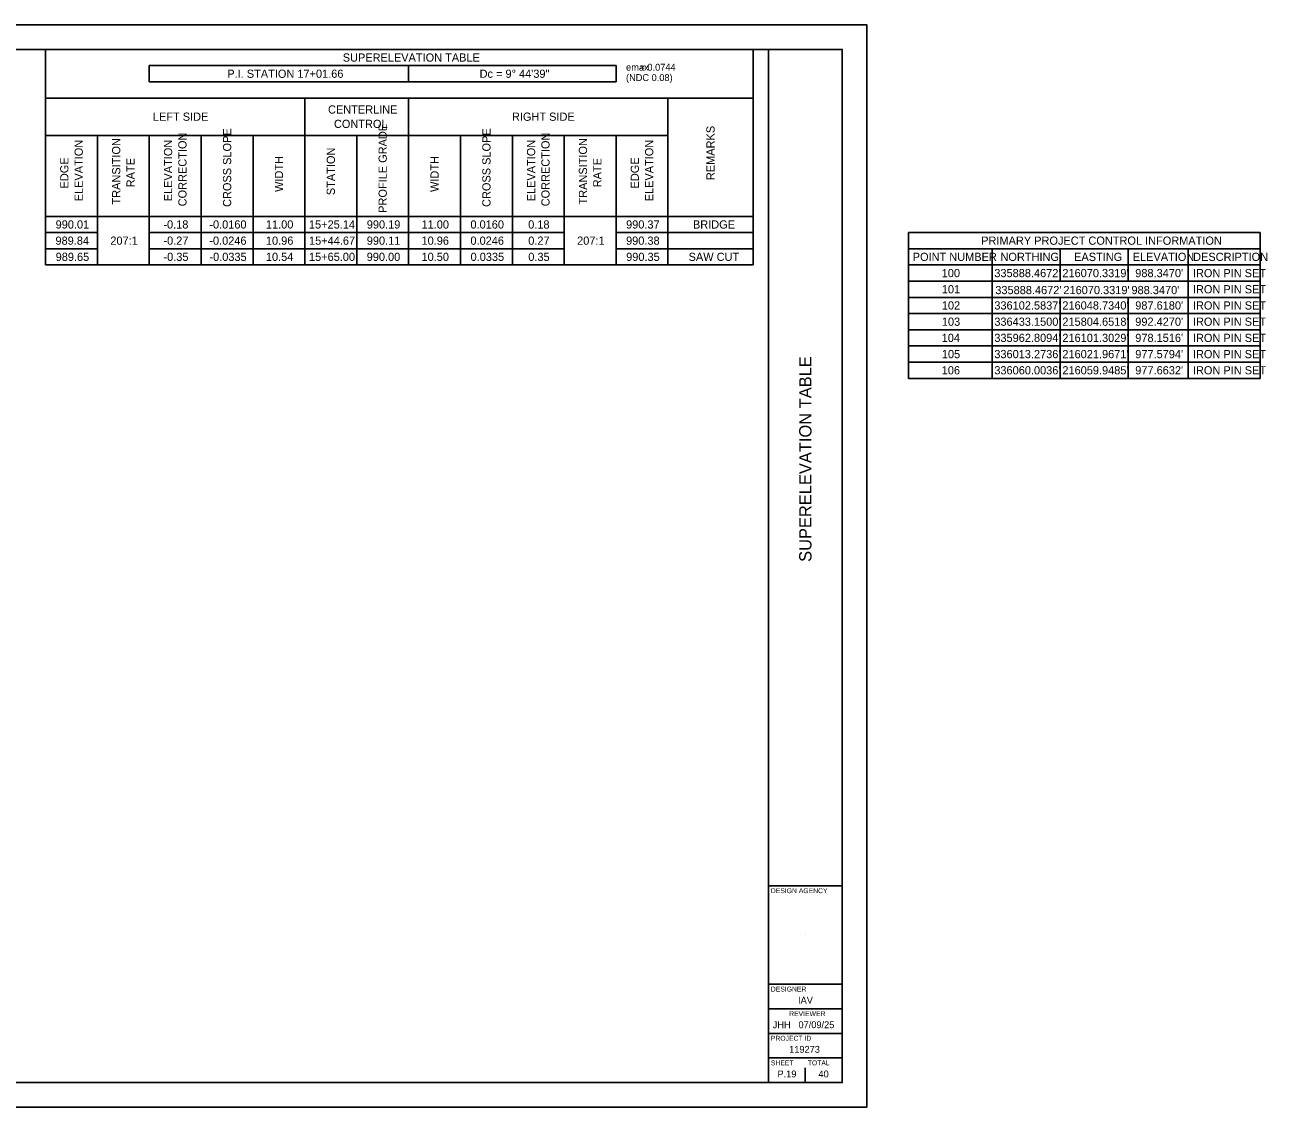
# Model space of a CAD drawing. Extents: x 0 to 42.1, y 0 to 22.
# Drawn here: x 16.89 to 42.14, y 0 to 22 of the extents above; entities that cross this region are included whole.
import ezdxf

# ---------------------------------------------------------------- set-up
doc = ezdxf.new("R2010")
doc.units = 0
for name, color, linetype in [('SH_Border', 7, 'Continuous'), ('SH_Cut_Line', 7, 'Continuous'), ('SH_Data', 7, 'Continuous'), ('SH_Text', 7, 'Continuous')]:
    doc.layers.add(name, color=color, linetype=linetype)

msp = doc.modelspace()

# ---------------------------------------------------------------- linework, layer by layer
at = {"layer": 'SH_Border'}
for p, q in [((32, 0.5), (32, 21.5)), ((32, 4.5), (33.5, 4.5)), ((32, 2.5), (33.5, 2.5)), ((32, 2), (33.5, 2)), ((32, 1.5), (33.5, 1.5)), ((32, 1), (33.5, 1))]:
    msp.add_line(p, q, dxfattribs=at)
msp.add_lwpolyline([(1.5, 21.5), (33.5, 21.5), (33.5, 0.5), (1.5, 0.5)], close=True, dxfattribs=at)
at = {"layer": 'SH_Cut_Line'}
msp.add_lwpolyline([(0, 0), (34, 0), (34, 22), (0, 22)], close=True, dxfattribs=at)
at = {"layer": 'SH_Data'}
for p, q in [((32.75, 3.5), (32.75, 3.5)), ((32.75, 0.5), (32.75, 0.8)), ((32.375, 0.675), (32.375, 0.675))]:
    msp.add_line(p, q, dxfattribs=at)
at = {"layer": 'SH_Text'}
for p, q in [((17.31, 21.5), (31.687, 21.5)), ((17.31, 21.5), (17.31, 17.119)), ((31.687, 21.5), (31.687, 17.119)), ((19.418, 21.171), (28.904, 21.171)), ((19.418, 21.171), (19.418, 20.841)), ((24.688, 21.171), (24.688, 20.841)), ((28.904, 21.171), (28.904, 20.841)), ((19.418, 20.841), (28.904, 20.841)), ((17.31, 20.512), (31.687, 20.512)), ((22.58, 20.512), (22.58, 17.119)), ((24.688, 20.512), (24.688, 17.119)), ((29.958, 20.512), (29.958, 17.119)), ((17.31, 19.754), (29.958, 19.754)), ((18.364, 19.754), (18.364, 17.119)), ((19.418, 19.754), (19.418, 17.119)), ((20.472, 19.754), (20.472, 17.119)), ((21.526, 19.754), (21.526, 17.119)), ((23.634, 19.754), (23.634, 17.119)), ((25.742, 19.754), (25.742, 17.119)), ((26.796, 19.754), (26.796, 17.119)), ((27.85, 19.754), (27.85, 17.119)), ((28.904, 19.754), (28.904, 17.119)), ((17.31, 18.107), (31.687, 18.107)), ((17.31, 17.778), (18.364, 17.778)), ((19.418, 17.778), (27.85, 17.778)), ((28.904, 17.778), (31.687, 17.778)), ((34.849, 17.778), (41.996, 17.778)), ((34.849, 17.778), (34.849, 14.814)), ((41.996, 17.778), (41.996, 14.814)), ((17.31, 17.449), (18.364, 17.449)), ((19.418, 17.449), (27.85, 17.449)), ((28.904, 17.449), (31.687, 17.449)), ((34.849, 17.449), (41.996, 17.449)), ((36.545, 17.449), (36.545, 14.814)), ((37.929, 17.449), (37.929, 16.79)), ((39.312, 17.449), (39.312, 16.79)), ((40.531, 17.449), (40.531, 14.814)), ((17.31, 17.119), (31.687, 17.119)), ((34.849, 17.119), (41.996, 17.119)), ((34.849, 16.79), (41.996, 16.79)), ((34.849, 16.461), (41.996, 16.461)), ((37.929, 16.461), (37.929, 14.814)), ((39.312, 16.461), (39.312, 14.814)), ((34.849, 16.131), (41.996, 16.131)), ((34.849, 15.802), (41.996, 15.802)), ((34.849, 15.472), (41.996, 15.472)), ((34.849, 15.143), (41.996, 15.143)), ((34.849, 14.814), (41.996, 14.814))]:
    msp.add_line(p, q, dxfattribs=at)

# ---------------------------------------------------------------- texts
at = {"layer": 'SH_Data'}
msp.add_text('SUPERELEVATION TABLE', height=0.25, rotation=90, dxfattribs=at).set_placement((32.875, 11.084))
for s, height, p in [('DESIGN AGENCY', 0.1, (32.05, 4.35)), ('DESIGNER', 0.1, (32.05, 2.35)), ('IAV', 0.14, (32.602, 2.105)), ('REVIEWER', 0.1, (32.422, 1.85)), ('JHH', 0.14, (32.087, 1.605)), ('07/09/25', 0.14, (32.611, 1.605)), ('PROJECT ID', 0.1, (32.05, 1.35)), ('119273', 0.14, (32.421, 1.105)), ('SHEET', 0.1, (32.05, 0.85)), ('TOTAL', 0.1, (32.8, 0.85)), ('P.19', 0.14, (32.184, 0.605)), ('40', 0.14, (33.017, 0.605))]:
    msp.add_text(s, height=height, dxfattribs=at).set_placement(p)
at = {"layer": 'SH_Text'}
for s, height, p in [('SUPERELEVATION TABLE', 0.16666, (23.349, 21.252)), (' = 0.0744', 0.14, (29.327, 21.068)), ('P.I. STATION 17+01.66', 0.16666, (21.003, 20.923)), ('Dc = 9° 44\'39"', 0.16666, (26.13, 20.923)), ('e', 0.14, (29.106, 21.068)), ('(NDC 0.08)', 0.14, (29.106, 20.858)), ('max', 0.14, (29.212, 21.068)), ('LEFT SIDE', 0.1667, (19.491, 20.05)), ('CENTERLINE ', 0.16666, (23.05, 20.196)), ('RIGHT SIDE', 0.1667, (26.788, 20.05)), ('CONTROL', 0.1667, (23.17, 19.904)), ('990.01', 0.1667, (17.514, 17.859)), ('-0.18', 0.1667, (19.704, 17.859)), ('-0.0160', 0.1667, (20.638, 17.859)), ('11.00', 0.1667, (21.788, 17.859)), ('15+25.14', 0.1667, (22.662, 17.859)), ('990.19', 0.1667, (23.838, 17.859)), ('11.00', 0.1667, (24.95, 17.859)), ('0.0160', 0.1667, (25.944, 17.859)), ('0.18', 0.1667, (27.118, 17.859)), ('990.37', 0.1667, (29.107, 17.859)), ('BRIDGE', 0.1667, (30.466, 17.859)), ('989.84', 0.1667, (17.511, 17.53)), ('207:1', 0.1667, (18.626, 17.53)), ('-0.27', 0.1667, (19.705, 17.53)), ('-0.0246', 0.1667, (20.638, 17.53)), ('10.96', 0.1667, (21.788, 17.53)), ('15+44.67', 0.1667, (22.664, 17.53)), ('990.11', 0.1667, (23.838, 17.53)), ('10.96', 0.1667, (24.95, 17.53)), ('0.0246', 0.1667, (25.944, 17.53)), ('0.27', 0.1667, (27.119, 17.53)), ('207:1', 0.1667, (28.112, 17.53)), ('990.38', 0.1667, (29.107, 17.53)), ('PRIMARY PROJECT CONTROL INFORMATION', 0.16666, (36.324, 17.53)), ('989.65', 0.1667, (17.515, 17.201)), ('-0.35', 0.1667, (19.706, 17.201)), ('-0.0335', 0.1667, (20.64, 17.201)), ('10.54', 0.1667, (21.787, 17.201)), ('15+65.00', 0.1667, (22.663, 17.201)), ('990.00', 0.1667, (23.836, 17.201)), ('10.50', 0.1667, (24.95, 17.201)), ('0.0335', 0.1667, (25.947, 17.201)), ('0.35', 0.1667, (27.12, 17.201)), ('990.35', 0.1667, (29.109, 17.201)), ('SAW CUT', 0.1667, (30.378, 17.201)), ('POINT NUMBER', 0.16666, (34.933, 17.201)), ('NORTHING', 0.1667, (36.716, 17.201)), ('EASTING', 0.1667, (38.212, 17.201)), ('ELEVATION', 0.1667, (39.404, 17.201)), ('DESCRIPTION', 0.16666, (40.631, 17.201)), ('100', 0.1667, (35.522, 16.871)), ("335888.4672'", 0.16666, (36.591, 16.871)), ("216070.3319'", 0.16666, (37.974, 16.871)), ("988.3470'", 0.1667, (39.455, 16.871)), ('IRON PIN SET', 0.16666, (40.627, 16.871)), ('101', 0.1667, (35.524, 16.542)), ("335888.4672'", 0.16666, (36.611, 16.526)), ("216070.3319'", 0.16666, (37.995, 16.526)), ("988.3470'", 0.1667, (39.378, 16.526)), ('IRON PIN SET', 0.16666, (40.627, 16.542)), ('102', 0.1667, (35.524, 16.213)), ("336102.5837'", 0.16666, (36.591, 16.213)), ("216048.7340'", 0.16666, (37.974, 16.213)), ("987.6180'", 0.1667, (39.455, 16.213)), ('IRON PIN SET', 0.16666, (40.627, 16.213)), ('103', 0.1667, (35.525, 15.883)), ("336433.1500'", 0.16666, (36.591, 15.883)), ("215804.6518'", 0.16666, (37.974, 15.883)), ("992.4270'", 0.1667, (39.455, 15.883)), ('IRON PIN SET', 0.16666, (40.627, 15.883)), ('104', 0.1667, (35.521, 15.554)), ("335962.8094'", 0.16666, (36.591, 15.554)), ("216101.3029'", 0.16666, (37.974, 15.554)), ("978.1516'", 0.1667, (39.455, 15.554)), ('IRON PIN SET', 0.16666, (40.627, 15.554)), ('105', 0.1667, (35.525, 15.224)), ("336013.2736'", 0.16666, (36.591, 15.224)), ("216021.9671'", 0.16666, (37.974, 15.224)), ("977.5794'", 0.1667, (39.455, 15.224)), ('IRON PIN SET', 0.16666, (40.627, 15.224)), ('106', 0.1667, (35.522, 14.895)), ("336060.0036'", 0.16666, (36.591, 14.895)), ("216059.9485'", 0.16666, (37.974, 14.895)), ("977.6632'", 0.1667, (39.455, 14.895)), ('IRON PIN SET', 0.16666, (40.627, 14.895))]:
    msp.add_text(s, height=height, dxfattribs=at).set_placement(p)
for s, height, p in [('PROFILE GRADE', 0.16666, (24.244, 18.179)), ('CORRECTION', 0.1667, (20.174, 18.311)), ('CROSS SLOPE', 0.16666, (21.082, 18.299)), ('CROSS SLOPE', 0.16666, (26.352, 18.299)), ('CORRECTION', 0.1667, (27.552, 18.311)), ('REMARKS', 0.1667, (30.906, 18.844)), ('ELEVATION', 0.1667, (18.066, 18.413)), ('TRANSITION ', 0.16666, (18.828, 18.348)), ('ELEVATION ', 0.1667, (19.882, 18.413)), ('STATION', 0.1667, (23.19, 18.538)), ('ELEVATION ', 0.1667, (27.26, 18.413)), ('TRANSITION ', 0.16666, (28.314, 18.348)), ('ELEVATION', 0.1667, (29.66, 18.413)), ('EDGE ', 0.1667, (17.774, 18.674)), ('RATE', 0.1667, (19.12, 18.698)), ('WIDTH', 0.1667, (22.136, 18.603)), ('WIDTH', 0.1667, (25.298, 18.603)), ('RATE', 0.1667, (28.606, 18.698)), ('EDGE ', 0.1667, (29.368, 18.674))]:
    msp.add_text(s, height=height, rotation=90, dxfattribs=at).set_placement(p)

doc.saveas('drawing.dxf')
